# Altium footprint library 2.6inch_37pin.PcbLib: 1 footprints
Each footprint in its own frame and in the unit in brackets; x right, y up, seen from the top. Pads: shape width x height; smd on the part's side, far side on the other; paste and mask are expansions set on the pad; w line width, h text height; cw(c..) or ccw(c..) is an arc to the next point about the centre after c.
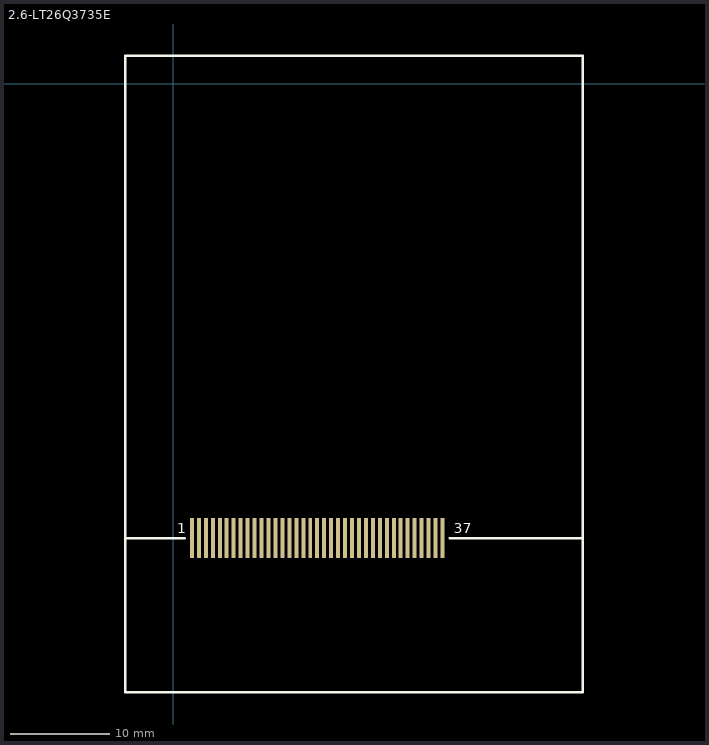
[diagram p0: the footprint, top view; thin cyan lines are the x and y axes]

## 2.6-LT26Q3735E [mm] "2.6inch TFT LCD"
pads (37):
  rect 0.4x4 smd: 1(1.874,-45.706) 2(2.574,-45.706) 3(3.274,-45.706) 4(3.974,-45.706) 5(4.674,-45.706) 6(5.374,-45.706) 7(6.074,-45.706) 8(6.774,-45.706) 9(7.474,-45.706) 10(8.174,-45.706) 11(8.874,-45.706) 12(9.574,-45.706) 13(10.274,-45.706) 14(10.974,-45.706) 15(11.674,-45.706) 16(12.374,-45.706) 17(13.074,-45.706) 18(13.774,-45.706) 19(14.474,-45.706) 20(15.174,-45.706) 21(15.874,-45.706) 22(16.574,-45.706) 23(17.274,-45.706) 24(17.974,-45.706) 25(18.674,-45.706) 26(19.374,-45.706) 27(20.074,-45.706) 28(20.774,-45.706) 29(21.474,-45.706) 30(22.174,-45.706) 31(22.874,-45.706) 32(23.574,-45.706) 33(24.274,-45.706) 34(24.974,-45.706) 35(25.674,-45.706) 36(26.374,-45.706) 37(27.074,-45.706)
Top Overlay:
  lines w0.254: -4.812,-45.706 1.143,-45.706 ; 27.813,-45.706 41.16,-45.706 ; -4.826,-61.206 41.174,-61.206 41.174,2.794 -4.826,2.794 -4.826,-61.206
  text "37" at 28.194,-45.212 h1.02
  text "1" at 0.381,-45.212 h1.02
